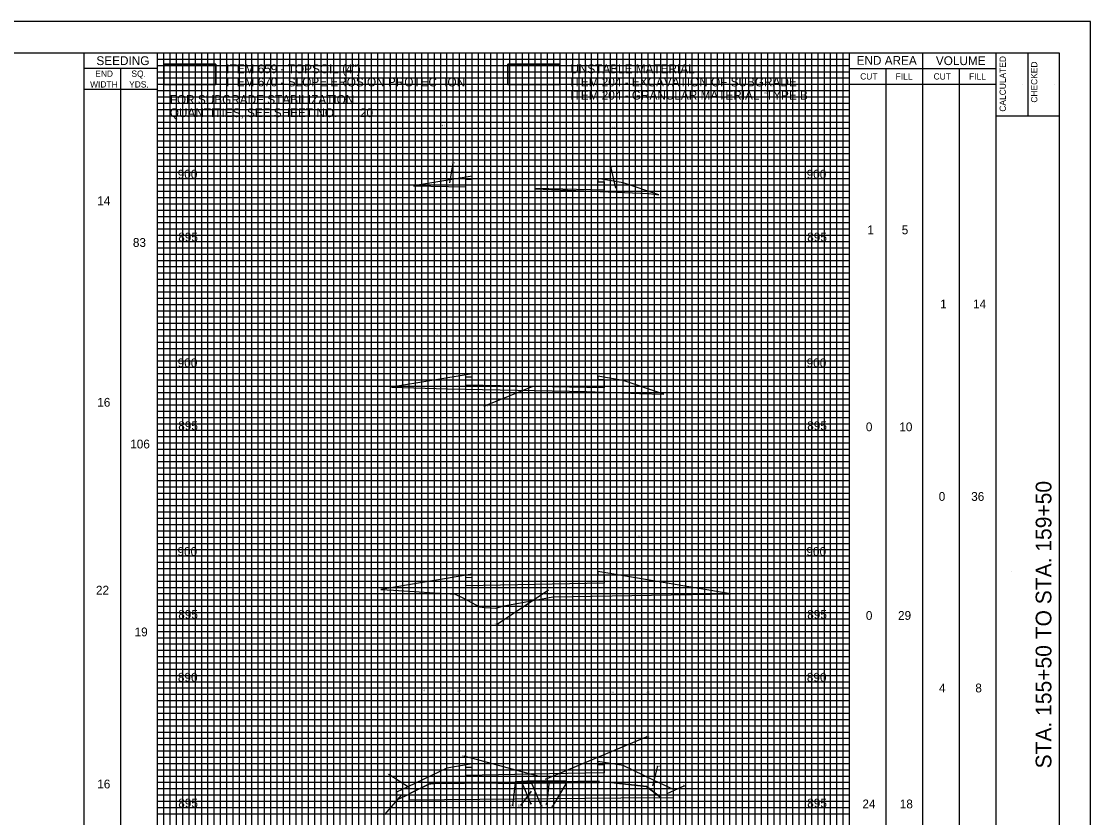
# Model space of a CAD drawing. Extents: x -73 to 160, y -2 to 1877.
# Drawn here: x 75 to 160, y 274.2 to 337.5 of the extents above; entities that cross this region are included whole.
import ezdxf

# ---------------------------------------------------------------- set-up
doc = ezdxf.new("R2010")
doc.units = 0
for name, color, linetype in [('DR_P_Flood_Boundary', 7, 'Continuous'), ('GK_Cells', 7, 'Continuous'), ('PV_P_Drive', 7, 'Continuous'), ('PV_P_EOP', 7, 'Continuous'), ('RD_X_Fence', 7, 'Continuous'), ('TX_X_5', 7, 'Continuous'), ('UT_P_Water_Cells', 7, 'Continuous'), ('XS_P_Pavt_Surface', 7, 'Continuous'), ('XS_P_Special_Benching', 7, 'Continuous'), ('XS_X_Ground_Line', 7, 'Continuous')]:
    doc.layers.add(name, color=color, linetype=linetype)

msp = doc.modelspace()

# ---------------------------------------------------------------- linework, layer by layer
at = {"layer": 'DR_P_Flood_Boundary'}
for p, q in [((90.832, 230), (90.832, 335)), ((95.832, 230), (95.832, 335)), ((100.832, 230), (100.832, 335)), ((105.832, 230), (105.832, 335)), ((110.832, 230), (110.832, 335)), ((115.832, 230), (115.832, 335)), ((120.832, 230), (120.832, 335)), ((125.832, 230), (125.832, 335)), ((130.832, 230), (130.832, 335)), ((135.832, 230), (135.832, 335)), ((85.832, 330), (140.832, 330)), ((85.832, 325), (140.832, 325)), ((85.832, 320), (140.832, 320)), ((85.832, 315), (140.832, 315)), ((85.832, 310), (140.832, 310)), ((85.832, 305), (140.832, 305)), ((85.832, 300), (140.832, 300)), ((85.832, 295), (140.832, 295)), ((85.832, 290), (140.832, 290)), ((85.832, 285), (140.832, 285)), ((85.832, 280), (140.832, 280)), ((85.832, 275), (140.832, 275))]:
    msp.add_line(p, q, dxfattribs=at)
at = {"layer": 'GK_Cells'}
for p, q in [((152.5, 230), (152.5, 335)), ((155, 335), (155, 330)), ((152.5, 330), (157.5, 330))]:
    msp.add_line(p, q, dxfattribs=at)
msp.add_lwpolyline([(0, 335), (157.5, 335), (157.5, 230), (0, 230)], close=True, dxfattribs=at)
at = {"layer": 'PV_P_Drive'}
msp.add_lwpolyline([(86.322, 334.094), (90.463, 334.094), (90.463, 332.479), (86.322, 332.479)], close=True, dxfattribs=at)
msp.add_lwpolyline([(86.322, 332.479), (90.463, 332.479), (90.463, 334.094), (86.322, 334.094), (86.322, 332.479)], dxfattribs=at)
at = {"layer": 'PV_P_EOP'}
msp.add_lwpolyline([(113.672, 334.094), (117.812, 334.094), (117.812, 332.479), (113.672, 332.479)], close=True, dxfattribs=at)
msp.add_lwpolyline([(113.672, 332.479), (117.812, 332.479), (117.812, 334.094), (113.672, 334.094), (113.672, 332.479)], dxfattribs=at)
at = {"layer": 'RD_X_Fence'}
for p, q in [((109.047, 324.653), (109.318, 326.239)), ((122.268, 324.25), (121.863, 325.97)), ((110.832, 325.2), (106.183, 324.425)), ((110.332, 324.96), (110.832, 324.95)), ((110.332, 324.339), (110.332, 324.96)), ((122.832, 324.667), (120.832, 325)), ((120.832, 324.75), (121.332, 324.74)), ((121.332, 324.74), (121.332, 324.073)), ((106.183, 324.425), (110.332, 324.339)), ((121.332, 324.073), (115.833, 324.206)), ((125.68, 323.717), (122.832, 324.667)), ((110.832, 309.48), (104.43, 308.413)), ((110.332, 308.573), (110.332, 309.24)), ((110.332, 309.24), (110.832, 309.23)), ((121.332, 308.353), (110.332, 308.573)), ((122.832, 308.947), (120.832, 309.28)), ((120.832, 309.03), (121.332, 309.02)), ((121.332, 309.02), (121.332, 308.353)), ((126.071, 307.867), (122.832, 308.947)), ((115.656, 308.475), (111.867, 306.93)), ((110.832, 293.55), (103.569, 292.339)), ((110.332, 293.29), (110.832, 293.3)), ((110.332, 292.623), (110.332, 293.29)), ((131.363, 291.995), (120.832, 293.75)), ((120.832, 293.5), (121.332, 293.51)), ((121.332, 293.51), (121.332, 292.843)), ((121.332, 292.843), (110.332, 292.623)), ((116.917, 292.288), (112.811, 289.544)), ((116.661, 277.26), (124.735, 280.649)), ((116.166, 277.466), (110.189, 279.079)), ((110.832, 278.46), (108.832, 278.127)), ((110.332, 278.2), (110.832, 278.21)), ((110.332, 277.533), (110.332, 278.2)), ((122.832, 278.327), (120.832, 278.66)), ((120.832, 278.41), (121.332, 278.42)), ((121.332, 278.42), (121.332, 277.753)), ((125.208, 276.713), (125.607, 278.292)), ((105.848, 276.57), (104.212, 277.617)), ((107.442, 276.871), (105.832, 276.085)), ((105.832, 276.085), (107.442, 276.871)), ((107.442, 276.871), (107.56, 276.872)), ((107.56, 276.872), (109.056, 277.021)), ((109.056, 277.021), (112.908, 276.921)), ((112.908, 276.921), (114.253, 277.026)), ((112.908, 276.921), (115.548, 276.945)), ((114.257, 276.966), (114.045, 275.142)), ((115.182, 277.098), (114.253, 277.05)), ((114.253, 277.026), (114.756, 277.065)), ((114.256, 277), (114.257, 277)), ((114.257, 277), (115.183, 277.012)), ((115.514, 276.29), (114.666, 275.162)), ((114.756, 277.065), (115.182, 277.098)), ((114.758, 277.041), (115.489, 275.289)), ((115.833, 277.097), (115.182, 277.098)), ((115.183, 277.012), (115.834, 277.021)), ((115.501, 277.057), (116.309, 275.142)), ((115.548, 276.945), (115.518, 277.017)), ((115.548, 276.945), (120.933, 276.994)), ((118.363, 277.093), (115.833, 277.097)), ((115.834, 277.021), (116.953, 277.017)), ((116.959, 277.066), (116.749, 275.228)), ((116.953, 277.017), (116.959, 277.066)), ((116.959, 277.017), (118.363, 277.013)), ((118.363, 277.013), (117.208, 275.062)), ((118.363, 277.008), (120.933, 276.994)), ((121.69, 277.001), (120.933, 276.994)), ((120.933, 276.994), (121.69, 277.001)), ((122.539, 276.902), (121.69, 277.001)), ((121.69, 277.001), (122.539, 276.902)), ((124.685, 276.662), (122.539, 276.902)), ((122.539, 276.902), (124.685, 276.662)), ((125.832, 275.79), (124.685, 276.662)), ((126.331, 276.108), (127.743, 276.737)), ((105.226, 276.006), (103.889, 274.46)), ((104.832, 276.223), (104.832, 275.597)), ((105.832, 276.085), (105.832, 275.606)), ((105.832, 276.065), (105.832, 276.085)), ((125.832, 275.789), (125.832, 275.79))]:
    msp.add_line(p, q, dxfattribs=at)
for points in [[(110.832, 324.95), (110.832, 325.096), (110.832, 325.2)], [(120.832, 325), (120.832, 324.896), (120.832, 324.75)], [(115.833, 324.206), (115.832, 324.187)], [(115.832, 324.187), (124.878, 323.808), (125.68, 323.717)], [(110.832, 309.23), (110.832, 309.376), (110.832, 309.48)], [(120.832, 309.28), (120.832, 309.176), (120.832, 309.03)], [(104.43, 308.413), (108.869, 308.289), (115.833, 308.146), (119.923, 308.062), (124.147, 307.908), (126.071, 307.867)], [(110.832, 293.3), (110.832, 293.446), (110.832, 293.55)], [(120.832, 293.75), (120.832, 293.646), (120.832, 293.5)], [(103.569, 292.339), (103.568, 292.322)], [(103.568, 292.322), (104.594, 292.272), (109.489, 291.952), (110.137, 291.632), (111.422, 290.964), (111.817, 290.889), (112.717, 290.85), (113.352, 291.024), (115.833, 291.489), (117.248, 291.74), (131.363, 291.995)], [(108.832, 278.127), (105.726, 276.648), (104.832, 276.223)], [(110.832, 278.21), (110.832, 278.356), (110.832, 278.46)], [(120.832, 278.66), (120.832, 278.556), (120.832, 278.41)], [(126.832, 276.423), (125.317, 277.144), (122.832, 278.327)], [(121.332, 277.753), (115.53, 277.637), (110.332, 277.533)], [(120.933, 276.994), (112.908, 276.921), (107.56, 276.872), (107.442, 276.871)], [(115.518, 277.017), (115.502, 277.016), (115.183, 277.012), (112.908, 276.982)], [(112.908, 276.982), (112.908, 276.921)], [(114.253, 277.05), (114.256, 277)], [(115.182, 277.098), (115.183, 277.012)], [(115.183, 277.012), (115.182, 277.098)], [(115.182, 277.098), (115.501, 277.06), (115.834, 277.021)], [(120.932, 277.089), (115.834, 277.021), (115.547, 277.017)], [(115.547, 277.017), (115.548, 276.945)], [(115.834, 277.021), (115.833, 277.097)], [(115.833, 277.097), (115.834, 277.021)], [(115.834, 277.021), (118.363, 277.055), (118.363, 277.055)], [(116.959, 277.066), (116.959, 277.017)], [(118.363, 277.055), (118.363, 277.093)], [(118.363, 277.013), (118.363, 277.008)], [(120.933, 276.994), (120.932, 277.089)], [(124.685, 276.662), (125.832, 275.789), (126.832, 275.765)], [(126.832, 275.765), (126.832, 276.332), (126.832, 276.423)], [(104.832, 275.597), (104.9, 275.629), (105.832, 276.065)], [(105.832, 275.606), (122.656, 275.76), (125.832, 275.789)]]:
    msp.add_lwpolyline(points, dxfattribs=at)
at = {"layer": 'TX_X_5'}
msp.add_lwpolyline([(-10, 227.5), (160, 227.5), (160, 337.5), (-10, 337.5)], close=True, dxfattribs=at)
at = {"layer": 'UT_P_Water_Cells'}
for p, q in [((86.332, 230), (86.332, 335)), ((86.832, 230), (86.832, 335)), ((87.332, 230), (87.332, 335)), ((87.832, 230), (87.832, 335)), ((88.332, 230), (88.332, 335)), ((88.832, 230), (88.832, 335)), ((89.332, 230), (89.332, 335)), ((89.832, 230), (89.832, 335)), ((90.332, 230), (90.332, 335)), ((91.332, 230), (91.332, 335)), ((91.832, 230), (91.832, 335)), ((92.332, 230), (92.332, 335)), ((92.832, 230), (92.832, 335)), ((93.332, 230), (93.332, 335)), ((93.832, 230), (93.832, 335)), ((94.332, 230), (94.332, 335)), ((94.832, 230), (94.832, 335)), ((95.332, 230), (95.332, 335)), ((96.332, 230), (96.332, 335)), ((96.832, 230), (96.832, 335)), ((97.332, 230), (97.332, 335)), ((97.832, 230), (97.832, 335)), ((98.332, 230), (98.332, 335)), ((98.832, 230), (98.832, 335)), ((99.332, 230), (99.332, 335)), ((99.832, 230), (99.832, 335)), ((100.332, 230), (100.332, 335)), ((101.332, 230), (101.332, 335)), ((101.832, 230), (101.832, 335)), ((102.332, 230), (102.332, 335)), ((102.832, 230), (102.832, 335)), ((103.332, 230), (103.332, 335)), ((103.832, 230), (103.832, 335)), ((104.332, 230), (104.332, 335)), ((104.832, 230), (104.832, 335)), ((105.332, 230), (105.332, 335)), ((106.332, 230), (106.332, 335)), ((106.832, 230), (106.832, 335)), ((107.332, 230), (107.332, 335)), ((107.832, 230), (107.832, 335)), ((108.332, 230), (108.332, 335)), ((108.832, 230), (108.832, 335)), ((109.332, 230), (109.332, 335)), ((109.832, 230), (109.832, 335)), ((110.332, 230), (110.332, 335)), ((111.332, 230), (111.332, 335)), ((111.832, 230), (111.832, 335)), ((112.332, 230), (112.332, 335)), ((112.832, 230), (112.832, 335)), ((113.332, 230), (113.332, 335)), ((113.832, 230), (113.832, 335)), ((114.332, 230), (114.332, 335)), ((114.832, 230), (114.832, 335)), ((115.332, 230), (115.332, 335)), ((116.332, 230), (116.332, 335)), ((116.832, 230), (116.832, 335)), ((117.332, 230), (117.332, 335)), ((117.832, 230), (117.832, 335)), ((118.332, 230), (118.332, 335)), ((118.832, 230), (118.832, 335)), ((119.332, 230), (119.332, 335)), ((119.832, 230), (119.832, 335)), ((120.332, 230), (120.332, 335)), ((121.332, 230), (121.332, 335)), ((121.832, 230), (121.832, 335)), ((122.332, 230), (122.332, 335)), ((122.832, 230), (122.832, 335)), ((123.332, 230), (123.332, 335)), ((123.832, 230), (123.832, 335)), ((124.332, 230), (124.332, 335)), ((124.832, 230), (124.832, 335)), ((125.332, 230), (125.332, 335)), ((126.332, 230), (126.332, 335)), ((126.832, 230), (126.832, 335)), ((127.332, 230), (127.332, 335)), ((127.832, 230), (127.832, 335)), ((128.332, 230), (128.332, 335)), ((128.832, 230), (128.832, 335)), ((129.332, 230), (129.332, 335)), ((129.832, 230), (129.832, 335)), ((130.332, 230), (130.332, 335)), ((131.332, 230), (131.332, 335)), ((131.832, 230), (131.832, 335)), ((132.332, 230), (132.332, 335)), ((132.832, 230), (132.832, 335)), ((133.332, 230), (133.332, 335)), ((133.832, 230), (133.832, 335)), ((134.332, 230), (134.332, 335)), ((134.832, 230), (134.832, 335)), ((135.332, 230), (135.332, 335)), ((136.332, 230), (136.332, 335)), ((136.832, 230), (136.832, 335)), ((137.332, 230), (137.332, 335)), ((137.832, 230), (137.832, 335)), ((138.332, 230), (138.332, 335)), ((138.832, 230), (138.832, 335)), ((139.332, 230), (139.332, 335)), ((139.832, 230), (139.832, 335)), ((140.332, 230), (140.332, 335)), ((85.832, 334.5), (140.832, 334.5)), ((85.832, 334), (140.832, 334)), ((85.832, 333.5), (140.832, 333.5)), ((85.832, 333), (140.832, 333)), ((85.832, 332.5), (140.832, 332.5)), ((85.832, 332), (140.832, 332)), ((85.832, 331.5), (140.832, 331.5)), ((85.832, 331), (140.832, 331)), ((85.832, 330.5), (140.832, 330.5)), ((85.832, 329.5), (140.832, 329.5)), ((85.832, 329), (140.832, 329)), ((85.832, 328.5), (140.832, 328.5)), ((85.832, 328), (140.832, 328)), ((85.832, 327.5), (140.832, 327.5)), ((85.832, 327), (140.832, 327)), ((85.832, 326.5), (140.832, 326.5)), ((85.832, 326), (140.832, 326)), ((85.832, 325.5), (140.832, 325.5)), ((85.832, 324.5), (140.832, 324.5)), ((85.832, 324), (140.832, 324)), ((85.832, 323.5), (140.832, 323.5)), ((85.832, 323), (140.832, 323)), ((85.832, 322.5), (140.832, 322.5)), ((85.832, 322), (140.832, 322)), ((85.832, 321.5), (140.832, 321.5)), ((85.832, 321), (140.832, 321)), ((85.832, 320.5), (140.832, 320.5)), ((85.832, 319.5), (140.832, 319.5)), ((85.832, 319), (140.832, 319)), ((85.832, 318.5), (140.832, 318.5)), ((85.832, 318), (140.832, 318)), ((85.832, 317.5), (140.832, 317.5)), ((85.832, 317), (140.832, 317)), ((85.832, 316.5), (140.832, 316.5)), ((85.832, 316), (140.832, 316)), ((85.832, 315.5), (140.832, 315.5)), ((85.832, 314.5), (140.832, 314.5)), ((85.832, 314), (140.832, 314)), ((85.832, 313.5), (140.832, 313.5)), ((85.832, 313), (140.832, 313)), ((85.832, 312.5), (140.832, 312.5)), ((85.832, 312), (140.832, 312)), ((85.832, 311.5), (140.832, 311.5)), ((85.832, 311), (140.832, 311)), ((85.832, 310.5), (140.832, 310.5)), ((85.832, 309.5), (140.832, 309.5)), ((85.832, 309), (140.832, 309)), ((85.832, 308.5), (140.832, 308.5)), ((85.832, 308), (140.832, 308)), ((85.832, 307.5), (140.832, 307.5)), ((85.832, 307), (140.832, 307)), ((85.832, 306.5), (140.832, 306.5)), ((85.832, 306), (140.832, 306)), ((85.832, 305.5), (140.832, 305.5)), ((85.832, 304.5), (140.832, 304.5)), ((85.832, 304), (140.832, 304)), ((85.832, 303.5), (140.832, 303.5)), ((85.832, 303), (140.832, 303)), ((85.832, 302.5), (140.832, 302.5)), ((85.832, 302), (140.832, 302)), ((85.832, 301.5), (140.832, 301.5)), ((85.832, 301), (140.832, 301)), ((85.832, 300.5), (140.832, 300.5)), ((85.832, 299.5), (140.832, 299.5)), ((85.832, 299), (140.832, 299)), ((85.832, 298.5), (140.832, 298.5)), ((85.832, 298), (140.832, 298)), ((85.832, 297.5), (140.832, 297.5)), ((85.832, 297), (140.832, 297)), ((85.832, 296.5), (140.832, 296.5)), ((85.832, 296), (140.832, 296)), ((85.832, 295.5), (140.832, 295.5)), ((85.832, 294.5), (140.832, 294.5)), ((85.832, 294), (140.832, 294)), ((85.832, 293.5), (140.832, 293.5)), ((85.832, 293), (140.832, 293)), ((85.832, 292.5), (140.832, 292.5)), ((85.832, 292), (140.832, 292)), ((85.832, 291.5), (140.832, 291.5)), ((85.832, 291), (140.832, 291)), ((85.832, 290.5), (140.832, 290.5)), ((85.832, 289.5), (140.832, 289.5)), ((85.832, 289), (140.832, 289)), ((85.832, 288.5), (140.832, 288.5)), ((85.832, 288), (140.832, 288)), ((85.832, 287.5), (140.832, 287.5)), ((85.832, 287), (140.832, 287)), ((85.832, 286.5), (140.832, 286.5)), ((85.832, 286), (140.832, 286)), ((85.832, 285.5), (140.832, 285.5)), ((85.832, 284.5), (140.832, 284.5)), ((85.832, 284), (140.832, 284)), ((85.832, 283.5), (140.832, 283.5)), ((85.832, 283), (140.832, 283)), ((85.832, 282.5), (140.832, 282.5)), ((85.832, 282), (140.832, 282)), ((85.832, 281.5), (140.832, 281.5)), ((85.832, 281), (140.832, 281)), ((85.832, 280.5), (140.832, 280.5)), ((85.832, 279.5), (140.832, 279.5)), ((85.832, 279), (140.832, 279)), ((85.832, 278.5), (140.832, 278.5)), ((85.832, 278), (140.832, 278)), ((85.832, 277.5), (140.832, 277.5)), ((85.832, 277), (140.832, 277)), ((85.832, 276.5), (140.832, 276.5)), ((85.832, 276), (140.832, 276)), ((85.832, 275.5), (140.832, 275.5)), ((85.832, 274.5), (140.832, 274.5))]:
    msp.add_line(p, q, dxfattribs=at)
at = {"layer": 'XS_X_Ground_Line'}
for p, q in [((80, 230), (80, 335)), ((85.832, 230), (85.832, 335)), ((140.832, 230), (140.832, 335)), ((146.667, 230), (146.667, 335)), ((85.832, 333.75), (80, 333.75)), ((82.916, 230), (82.916, 333.75)), ((140.832, 333.75), (152.5, 333.75)), ((143.75, 230), (143.75, 333.75)), ((149.583, 230), (149.583, 333.75)), ((140.832, 332.5), (152.5, 332.5)), ((154.6, 332.518), (154.6, 332.518)), ((157.1, 332.518), (157.1, 332.518)), ((85.832, 332.083), (80, 332.083)), ((153.75, 293.75), (153.75, 293.75)), ((156.258, 293.75), (156.258, 293.75))]:
    msp.add_line(p, q, dxfattribs=at)

# ---------------------------------------------------------------- texts
at = {"layer": 'RD_X_Fence'}
for s, p in [('2.5', (130.714, 331.394)), ('6.0', (134.076, 331.733)), ('4.7', (108.409, 329.152)), ('2.0', (121.906, 328.978)), ('3.0', (123.738, 328.978)), ('1.7', (109.199, 326.169)), ('2.8', (121.717, 325.9)), ('6.5', (108.018, 312.454)), ('2.0', (121.74, 311.938)), ('3.4', (124.113, 311.858)), ('10.4', (111.682, 306.86)), ('7.4', (107.58, 296.902)), ('10.7', (124.035, 296.48)), ('29.3', (112.605, 289.474)), ('4.0', (106.822, 284.224)), ('2.0', (109.655, 284.235)), ('2.0', (121.822, 284.096)), ('4.0', (124.692, 284.076)), ('18.3', (124.542, 280.579)), ('15.4', (110.011, 279.009)), ('2.1', (125.489, 278.222)), ('1.3', (104.093, 277.547)), ('0.6', (127.586, 276.667)), ('0.2', (113.893, 275.072)), ('22.9', (114.461, 275.092)), ('0.1', (115.363, 275.219)), ('0.1', (116.182, 275.072)), ('0.1', (116.623, 275.158)), ('0.4', (117.056, 274.992)), ('0.4', (103.737, 274.39))]:
    msp.add_text(s, height=0.14, dxfattribs=at).set_placement(p)
at = {"layer": 'XS_P_Pavt_Surface'}
for s, p in [('900', (87.427, 325)), ('900', (137.427, 325)), ('14', (81.031, 322.886)), ('895', (87.471, 320)), ('895', (137.471, 320)), ('1', (142.248, 320.575)), ('5', (144.984, 320.575)), ('83', (83.864, 319.569)), ('1', (148.04, 314.679)), ('14', (150.653, 314.679)), ('900', (87.427, 310)), ('900', (137.427, 310)), ('16', (81.029, 306.864)), ('895', (87.471, 305)), ('895', (137.471, 305)), ('0', (142.133, 304.912)), ('10', (144.791, 304.912)), ('106', (83.652, 303.547)), ('0', (147.925, 299.376)), ('36', (150.507, 299.376)), ('900', (87.41, 295)), ('900', (137.41, 295)), ('22', (80.929, 291.926)), ('895', (87.471, 290)), ('895', (137.471, 290)), ('0', (142.133, 289.919)), ('29', (144.689, 289.919)), ('19', (83.999, 288.609)), ('890', (87.443, 285)), ('890', (137.443, 285)), ('4', (147.947, 284.15)), ('8', (150.835, 284.15)), ('16', (81.029, 276.515)), ('895', (87.471, 275)), ('895', (137.471, 275)), ('24', (141.857, 274.93)), ('18', (144.83, 274.93))]:
    msp.add_text(s, height=0.7, dxfattribs=at).set_placement(p)
at = {"layer": 'XS_P_Special_Benching'}
for s, p in [('ITEM 659 - TOPSOIL (4")', (91.291, 333.38)), ('UNSTABLE MATERIAL', (118.64, 333.38)), ('ITEM 670 - SLOPE EROSION PROTECTION', (91.291, 332.33)), ('ITEM 204 - EXCAVATION OF SUBGRADE', (118.64, 332.33)), ('FOR SUBGRADE STABILIZATION', (86.798, 330.939)), ('ITEM 204 - GRANULAR MATERIAL, TYPE B', (118.64, 331.28)), ('QUANTITIES, SEE SHEET NO.', (86.798, 329.889)), ('20', (101.916, 329.889))]:
    msp.add_text(s, height=0.7, dxfattribs=at).set_placement(p)
at = {"layer": 'XS_X_Ground_Line'}
for s, height, p in [('SEEDING', 0.7, (80.964, 334.025)), ('END AREA', 0.7, (141.394, 334.047)), ('VOLUME', 0.7, (147.698, 334.025)), ('END', 0.5, (80.87, 333.092)), ('SQ.', 0.5, (83.748, 333.092)), ('CUT', 0.5, (141.683, 332.875)), ('FILL', 0.5, (144.502, 332.875)), ('CUT', 0.5, (147.517, 332.875)), ('FILL', 0.5, (150.335, 332.875)), ('WIDTH', 0.5, (80.462, 332.242)), ('YDS.', 0.5, (83.563, 332.242))]:
    msp.add_text(s, height=height, dxfattribs=at).set_placement(p)
for s, height, p in [('CALCULATED', 0.5, (153.262, 330.323)), ('CHECKED', 0.5, (155.762, 331.04)), ('STA. 155+50 TO STA. 159+50', 1.25, (156.883, 278.105))]:
    msp.add_text(s, height=height, rotation=90, dxfattribs=at).set_placement(p)

doc.saveas('drawing.dxf')
